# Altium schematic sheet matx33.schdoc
size 594 x 419 mm; Symbol: Drawing-Symbol_A4; @Project Name: Inverted_MAML_6x6; @Page Count: 1; @Update Date: 2026-06-14; @Create Date: 2026-06-14; @Schematic Name: Schematic1; @Page No: 1; @Page Name: P1; Company: EasyEDA.com; Version: V1.0; Page Size: A4; Drawn: Olle Welin; Device: Drawing-Symbol_A4; @Create Time: 14:27:06; @Update Time: 14:27:06; Border: 1; Width: 2338; Height: 1652; Region Start: 1; X Region Count: 6; Y Region Count: 4; Blade Width: 10; Title Block Position: 3
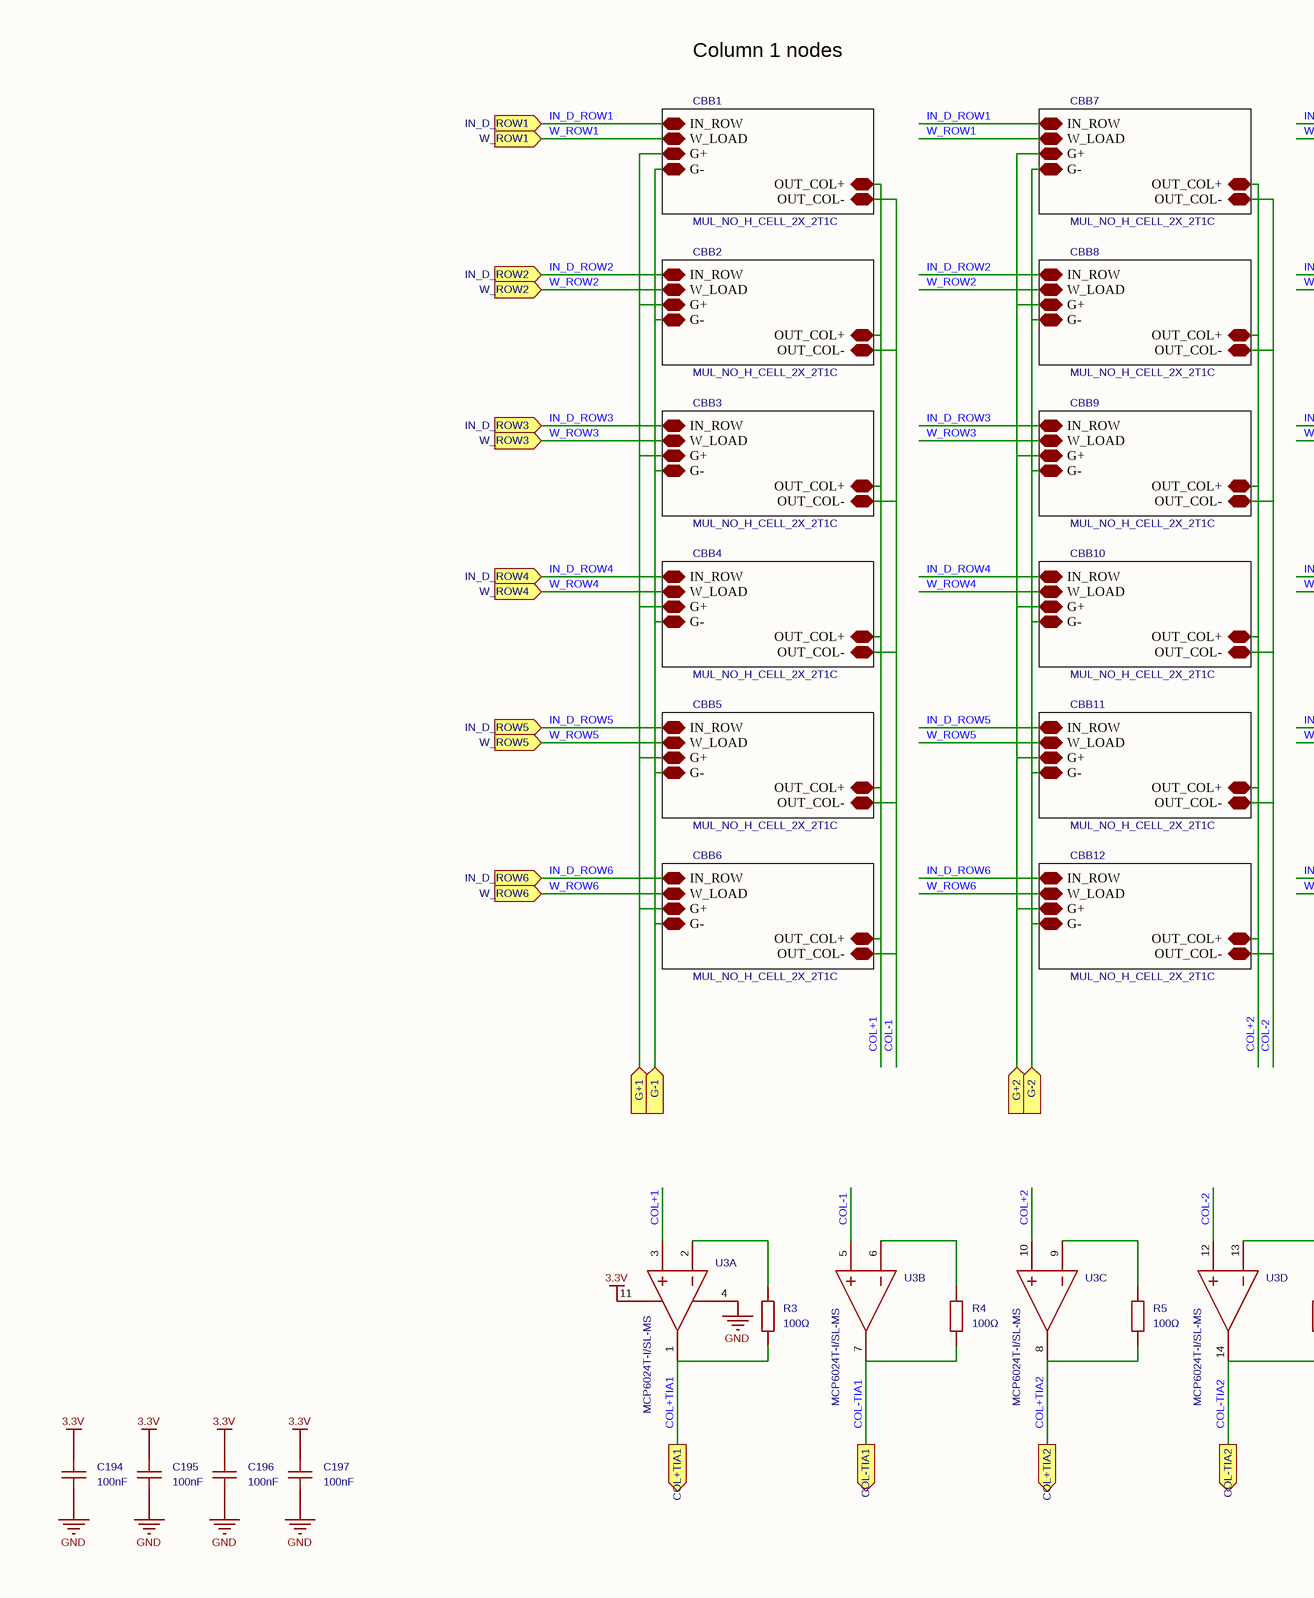
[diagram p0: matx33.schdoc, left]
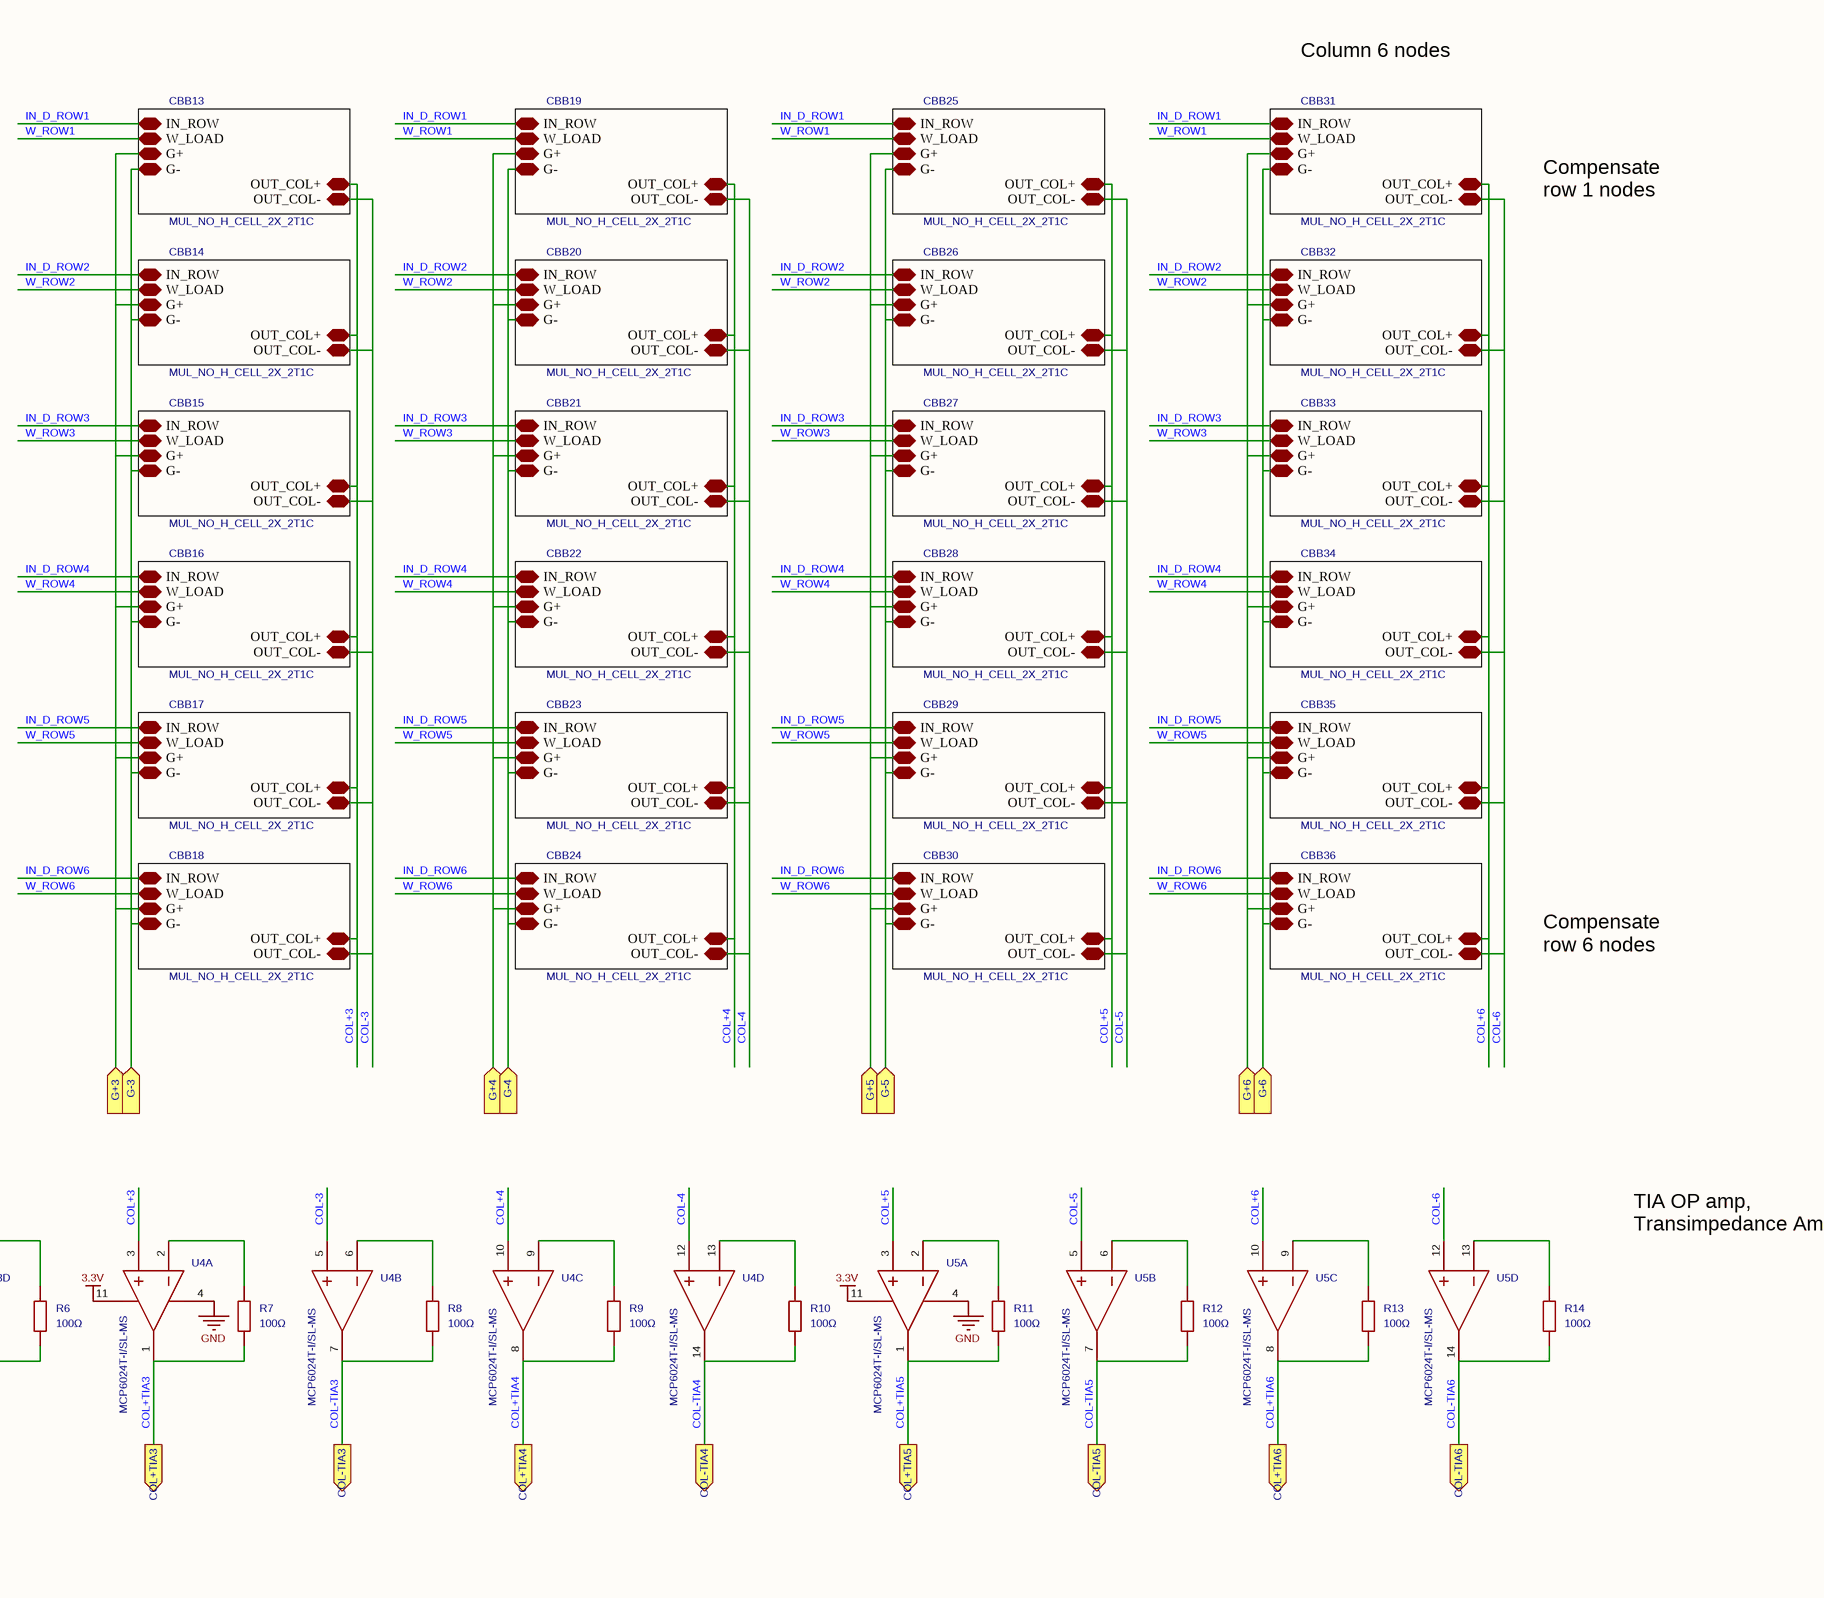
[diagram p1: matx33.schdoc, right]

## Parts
C194  100nF  [C0402]
C195  100nF  [C0402]
C196  100nF  [C0402]
C197  100nF  [C0402]
R3  100Ω  [R0402]
R4  100Ω  [R0402]
R5  100Ω  [R0402]
R6  100Ω  [R0402]
R7  100Ω  [R0402]
R8  100Ω  [R0402]
R9  100Ω  [R0402]
R10  100Ω  [R0402]
R11  100Ω  [R0402]
R12  100Ω  [R0402]
R13  100Ω  [R0402]
R14  100Ω  [R0402]
U3  MCP6024T-I/SL-MS  [SOIC-14_L8.7-W3.9-P1.27-LS6.0-BL-1]  (parts A,B,C,D of 4)
U4  MCP6024T-I/SL-MS  [SOIC-14_L8.7-W3.9-P1.27-LS6.0-BL-1]  (parts A,B,C,D of 4)
U5  MCP6024T-I/SL-MS  [SOIC-14_L8.7-W3.9-P1.27-LS6.0-BL-1]  (parts A,B,C,D of 4)

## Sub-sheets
CBB1 = matrix_33_MUL_CELL.schdoc: G+, W_LOAD, IN_ROW, G-, OUT_COL+, OUT_COL-  | Symbol: MUL_NO_H_CELL_2X_2T1C
CBB2 = matrix_33_MUL_CELL.schdoc: G+, W_LOAD, IN_ROW, G-, OUT_COL+, OUT_COL-  | Symbol: MUL_NO_H_CELL_2X_2T1C
CBB3 = matrix_33_MUL_CELL.schdoc: G+, W_LOAD, IN_ROW, G-, OUT_COL+, OUT_COL-  | Symbol: MUL_NO_H_CELL_2X_2T1C
CBB4 = matrix_33_MUL_CELL.schdoc: G+, W_LOAD, IN_ROW, G-, OUT_COL+, OUT_COL-  | Symbol: MUL_NO_H_CELL_2X_2T1C
CBB5 = matrix_33_MUL_CELL.schdoc: G+, W_LOAD, IN_ROW, G-, OUT_COL+, OUT_COL-  | Symbol: MUL_NO_H_CELL_2X_2T1C
CBB6 = matrix_33_MUL_CELL.schdoc: G+, W_LOAD, IN_ROW, G-, OUT_COL+, OUT_COL-  | Symbol: MUL_NO_H_CELL_2X_2T1C
CBB7 = matrix_33_MUL_CELL.schdoc: G+, W_LOAD, IN_ROW, G-, OUT_COL+, OUT_COL-  | Symbol: MUL_NO_H_CELL_2X_2T1C
CBB8 = matrix_33_MUL_CELL.schdoc: G+, W_LOAD, IN_ROW, G-, OUT_COL+, OUT_COL-  | Symbol: MUL_NO_H_CELL_2X_2T1C
CBB9 = matrix_33_MUL_CELL.schdoc: G+, W_LOAD, IN_ROW, G-, OUT_COL+, OUT_COL-  | Symbol: MUL_NO_H_CELL_2X_2T1C
CBB10 = matrix_33_MUL_CELL.schdoc: G+, W_LOAD, IN_ROW, G-, OUT_COL+, OUT_COL-  | Symbol: MUL_NO_H_CELL_2X_2T1C
CBB11 = matrix_33_MUL_CELL.schdoc: G+, W_LOAD, IN_ROW, G-, OUT_COL+, OUT_COL-  | Symbol: MUL_NO_H_CELL_2X_2T1C
CBB12 = matrix_33_MUL_CELL.schdoc: G+, W_LOAD, IN_ROW, G-, OUT_COL+, OUT_COL-  | Symbol: MUL_NO_H_CELL_2X_2T1C
CBB13 = matrix_33_MUL_CELL.schdoc: G+, W_LOAD, IN_ROW, G-, OUT_COL+, OUT_COL-  | Symbol: MUL_NO_H_CELL_2X_2T1C
CBB14 = matrix_33_MUL_CELL.schdoc: G+, W_LOAD, IN_ROW, G-, OUT_COL+, OUT_COL-  | Symbol: MUL_NO_H_CELL_2X_2T1C
CBB15 = matrix_33_MUL_CELL.schdoc: G+, W_LOAD, IN_ROW, G-, OUT_COL+, OUT_COL-  | Symbol: MUL_NO_H_CELL_2X_2T1C
CBB16 = matrix_33_MUL_CELL.schdoc: G+, W_LOAD, IN_ROW, G-, OUT_COL+, OUT_COL-  | Symbol: MUL_NO_H_CELL_2X_2T1C
CBB17 = matrix_33_MUL_CELL.schdoc: G+, W_LOAD, IN_ROW, G-, OUT_COL+, OUT_COL-  | Symbol: MUL_NO_H_CELL_2X_2T1C
CBB18 = matrix_33_MUL_CELL.schdoc: G+, W_LOAD, IN_ROW, G-, OUT_COL+, OUT_COL-  | Symbol: MUL_NO_H_CELL_2X_2T1C
CBB19 = matrix_33_MUL_CELL.schdoc: G+, W_LOAD, IN_ROW, G-, OUT_COL+, OUT_COL-  | Symbol: MUL_NO_H_CELL_2X_2T1C
CBB20 = matrix_33_MUL_CELL.schdoc: G+, W_LOAD, IN_ROW, G-, OUT_COL+, OUT_COL-  | Symbol: MUL_NO_H_CELL_2X_2T1C
CBB21 = matrix_33_MUL_CELL.schdoc: G+, W_LOAD, IN_ROW, G-, OUT_COL+, OUT_COL-  | Symbol: MUL_NO_H_CELL_2X_2T1C
CBB22 = matrix_33_MUL_CELL.schdoc: G+, W_LOAD, IN_ROW, G-, OUT_COL+, OUT_COL-  | Symbol: MUL_NO_H_CELL_2X_2T1C
CBB23 = matrix_33_MUL_CELL.schdoc: G+, W_LOAD, IN_ROW, G-, OUT_COL+, OUT_COL-  | Symbol: MUL_NO_H_CELL_2X_2T1C
CBB24 = matrix_33_MUL_CELL.schdoc: G+, W_LOAD, IN_ROW, G-, OUT_COL+, OUT_COL-  | Symbol: MUL_NO_H_CELL_2X_2T1C
CBB25 = matrix_33_MUL_CELL.schdoc: G+, W_LOAD, IN_ROW, G-, OUT_COL+, OUT_COL-  | Symbol: MUL_NO_H_CELL_2X_2T1C
CBB26 = matrix_33_MUL_CELL.schdoc: G+, W_LOAD, IN_ROW, G-, OUT_COL+, OUT_COL-  | Symbol: MUL_NO_H_CELL_2X_2T1C
CBB27 = matrix_33_MUL_CELL.schdoc: G+, W_LOAD, IN_ROW, G-, OUT_COL+, OUT_COL-  | Symbol: MUL_NO_H_CELL_2X_2T1C
CBB28 = matrix_33_MUL_CELL.schdoc: G+, W_LOAD, IN_ROW, G-, OUT_COL+, OUT_COL-  | Symbol: MUL_NO_H_CELL_2X_2T1C
CBB29 = matrix_33_MUL_CELL.schdoc: G+, W_LOAD, IN_ROW, G-, OUT_COL+, OUT_COL-  | Symbol: MUL_NO_H_CELL_2X_2T1C
CBB30 = matrix_33_MUL_CELL.schdoc: G+, W_LOAD, IN_ROW, G-, OUT_COL+, OUT_COL-  | Symbol: MUL_NO_H_CELL_2X_2T1C
CBB31 = matrix_33_MUL_CELL.schdoc: G+, W_LOAD, IN_ROW, G-, OUT_COL+, OUT_COL-  | Symbol: MUL_NO_H_CELL_2X_2T1C
CBB32 = matrix_33_MUL_CELL.schdoc: G+, W_LOAD, IN_ROW, G-, OUT_COL+, OUT_COL-  | Symbol: MUL_NO_H_CELL_2X_2T1C
CBB33 = matrix_33_MUL_CELL.schdoc: G+, W_LOAD, IN_ROW, G-, OUT_COL+, OUT_COL-  | Symbol: MUL_NO_H_CELL_2X_2T1C
CBB34 = matrix_33_MUL_CELL.schdoc: G+, W_LOAD, IN_ROW, G-, OUT_COL+, OUT_COL-  | Symbol: MUL_NO_H_CELL_2X_2T1C
CBB35 = matrix_33_MUL_CELL.schdoc: G+, W_LOAD, IN_ROW, G-, OUT_COL+, OUT_COL-  | Symbol: MUL_NO_H_CELL_2X_2T1C
CBB36 = matrix_33_MUL_CELL.schdoc: G+, W_LOAD, IN_ROW, G-, OUT_COL+, OUT_COL-  | Symbol: MUL_NO_H_CELL_2X_2T1C

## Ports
COL+TIA1 (out), COL+TIA2 (out), COL+TIA3 (out), COL+TIA4 (out), COL+TIA5 (out), COL+TIA6 (out), COL-TIA1 (out), COL-TIA2 (out), COL-TIA3 (out), COL-TIA4 (out), COL-TIA5 (out), COL-TIA6 (out), G+1 (in), G+2 (in), G+3 (in), G+4 (in), G+5 (in), G+6 (in), G-1 (in), G-2 (in), G-3 (in), G-4 (in), G-5 (in), G-6 (in), IN_D_ROW1 (in), IN_D_ROW2 (in), IN_D_ROW3 (in), IN_D_ROW4 (in), IN_D_ROW5 (in), IN_D_ROW6 (in), W_ROW1 (in), W_ROW2 (in), W_ROW3 (in), W_ROW4 (in), W_ROW5 (in), W_ROW6 (in)

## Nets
3.3V: C194.2 C195.2 C196.2 C197.2 U3.11(V-) U4.11(V-) U5.11(V-)
GND: C194.1 C195.1 C196.1 C197.1 U3.4(V+) U4.4(V+) U5.4(V+)
COL+1: U3.3(IN1+) ; sheet CBB1/OUT_COL+, sheet CBB3/OUT_COL+, sheet CBB5/OUT_COL+, sheet CBB2/OUT_COL+, sheet CBB4/OUT_COL+, sheet CBB6/OUT_COL+
COL+2: U3.10(IN3+) ; sheet CBB7/OUT_COL+, sheet CBB8/OUT_COL+, sheet CBB9/OUT_COL+, sheet CBB10/OUT_COL+, sheet CBB11/OUT_COL+, sheet CBB12/OUT_COL+
COL+3: U4.3(IN1+) ; sheet CBB13/OUT_COL+, sheet CBB14/OUT_COL+, sheet CBB15/OUT_COL+, sheet CBB16/OUT_COL+, sheet CBB17/OUT_COL+, sheet CBB18/OUT_COL+
COL+4: U4.10(IN3+) ; sheet CBB19/OUT_COL+, sheet CBB20/OUT_COL+, sheet CBB21/OUT_COL+, sheet CBB22/OUT_COL+, sheet CBB23/OUT_COL+, sheet CBB24/OUT_COL+
COL+5: U5.3(IN1+) ; sheet CBB25/OUT_COL+, sheet CBB26/OUT_COL+, sheet CBB27/OUT_COL+, sheet CBB28/OUT_COL+, sheet CBB29/OUT_COL+, sheet CBB30/OUT_COL+
COL+6: U5.10(IN3+) ; sheet CBB31/OUT_COL+, sheet CBB32/OUT_COL+, sheet CBB33/OUT_COL+, sheet CBB34/OUT_COL+, sheet CBB35/OUT_COL+, sheet CBB36/OUT_COL+
COL+TIA1: R3.1 U3.1(OUT1) ; port COL+TIA1
COL+TIA2: R5.1 U3.8(OUT3) ; port COL+TIA2
COL+TIA3: R7.1 U4.1(OUT1) ; port COL+TIA3
COL+TIA4: R9.1 U4.8(OUT3) ; port COL+TIA4
COL+TIA5: R11.1 U5.1(OUT1) ; port COL+TIA5
COL+TIA6: R13.1 U5.8(OUT3) ; port COL+TIA6
COL-1: U3.5(IN2+) ; sheet CBB1/OUT_COL-, sheet CBB3/OUT_COL-, sheet CBB5/OUT_COL-, sheet CBB2/OUT_COL-, sheet CBB4/OUT_COL-, sheet CBB6/OUT_COL-
COL-2: U3.12(IN4+) ; sheet CBB7/OUT_COL-, sheet CBB8/OUT_COL-, sheet CBB9/OUT_COL-, sheet CBB10/OUT_COL-, sheet CBB11/OUT_COL-, sheet CBB12/OUT_COL-
COL-3: U4.5(IN2+) ; sheet CBB13/OUT_COL-, sheet CBB14/OUT_COL-, sheet CBB15/OUT_COL-, sheet CBB16/OUT_COL-, sheet CBB17/OUT_COL-, sheet CBB18/OUT_COL-
COL-4: U4.12(IN4+) ; sheet CBB19/OUT_COL-, sheet CBB20/OUT_COL-, sheet CBB21/OUT_COL-, sheet CBB22/OUT_COL-, sheet CBB23/OUT_COL-, sheet CBB24/OUT_COL-
COL-5: U5.5(IN2+) ; sheet CBB25/OUT_COL-, sheet CBB26/OUT_COL-, sheet CBB27/OUT_COL-, sheet CBB28/OUT_COL-, sheet CBB29/OUT_COL-, sheet CBB30/OUT_COL-
COL-6: U5.12(IN4+) ; sheet CBB31/OUT_COL-, sheet CBB32/OUT_COL-, sheet CBB33/OUT_COL-, sheet CBB34/OUT_COL-, sheet CBB35/OUT_COL-, sheet CBB36/OUT_COL-
COL-TIA1: R4.1 U3.7(OUT2) ; port COL-TIA1
COL-TIA2: R6.1 U3.14(OUT4) ; port COL-TIA2
COL-TIA3: R8.1 U4.7(OUT2) ; port COL-TIA3
COL-TIA4: R10.1 U4.14(OUT4) ; port COL-TIA4
COL-TIA5: R12.1 U5.7(OUT2) ; port COL-TIA5
COL-TIA6: R14.1 U5.14(OUT4) ; port COL-TIA6
G+1: port G+1, sheet CBB1/G+, sheet CBB3/G+, sheet CBB5/G+, sheet CBB2/G+, sheet CBB4/G+, sheet CBB6/G+
G+2: port G+2, sheet CBB7/G+, sheet CBB8/G+, sheet CBB9/G+, sheet CBB10/G+, sheet CBB11/G+, sheet CBB12/G+
G+3: port G+3, sheet CBB13/G+, sheet CBB14/G+, sheet CBB15/G+, sheet CBB16/G+, sheet CBB17/G+, sheet CBB18/G+
G+4: port G+4, sheet CBB19/G+, sheet CBB20/G+, sheet CBB21/G+, sheet CBB22/G+, sheet CBB23/G+, sheet CBB24/G+
G+5: port G+5, sheet CBB25/G+, sheet CBB26/G+, sheet CBB27/G+, sheet CBB28/G+, sheet CBB29/G+, sheet CBB30/G+
G+6: port G+6, sheet CBB31/G+, sheet CBB32/G+, sheet CBB33/G+, sheet CBB34/G+, sheet CBB35/G+, sheet CBB36/G+
G-1: port G-1, sheet CBB1/G-, sheet CBB3/G-, sheet CBB5/G-, sheet CBB2/G-, sheet CBB4/G-, sheet CBB6/G-
G-2: port G-2, sheet CBB7/G-, sheet CBB8/G-, sheet CBB9/G-, sheet CBB10/G-, sheet CBB11/G-, sheet CBB12/G-
G-3: port G-3, sheet CBB13/G-, sheet CBB14/G-, sheet CBB15/G-, sheet CBB16/G-, sheet CBB17/G-, sheet CBB18/G-
G-4: port G-4, sheet CBB19/G-, sheet CBB20/G-, sheet CBB21/G-, sheet CBB22/G-, sheet CBB23/G-, sheet CBB24/G-
G-5: port G-5, sheet CBB25/G-, sheet CBB26/G-, sheet CBB27/G-, sheet CBB28/G-, sheet CBB29/G-, sheet CBB30/G-
G-6: port G-6, sheet CBB31/G-, sheet CBB32/G-, sheet CBB33/G-, sheet CBB34/G-, sheet CBB35/G-, sheet CBB36/G-
IN_D_ROW1: port IN_D_ROW1, sheet CBB1/IN_ROW, sheet CBB7/IN_ROW, sheet CBB13/IN_ROW, sheet CBB19/IN_ROW, sheet CBB25/IN_ROW, sheet CBB31/IN_ROW
IN_D_ROW2: port IN_D_ROW2, sheet CBB8/IN_ROW, sheet CBB14/IN_ROW, sheet CBB20/IN_ROW, sheet CBB26/IN_ROW, sheet CBB32/IN_ROW, sheet CBB2/IN_ROW
IN_D_ROW3: port IN_D_ROW3, sheet CBB3/IN_ROW, sheet CBB9/IN_ROW, sheet CBB15/IN_ROW, sheet CBB21/IN_ROW, sheet CBB27/IN_ROW, sheet CBB33/IN_ROW
IN_D_ROW4: port IN_D_ROW4, sheet CBB10/IN_ROW, sheet CBB16/IN_ROW, sheet CBB22/IN_ROW, sheet CBB28/IN_ROW, sheet CBB34/IN_ROW, sheet CBB4/IN_ROW
IN_D_ROW5: port IN_D_ROW5, sheet CBB5/IN_ROW, sheet CBB11/IN_ROW, sheet CBB17/IN_ROW, sheet CBB23/IN_ROW, sheet CBB29/IN_ROW, sheet CBB35/IN_ROW
IN_D_ROW6: port IN_D_ROW6, sheet CBB12/IN_ROW, sheet CBB18/IN_ROW, sheet CBB24/IN_ROW, sheet CBB30/IN_ROW, sheet CBB36/IN_ROW, sheet CBB6/IN_ROW
W_ROW1: port W_ROW1, sheet CBB1/W_LOAD, sheet CBB7/W_LOAD, sheet CBB13/W_LOAD, sheet CBB19/W_LOAD, sheet CBB25/W_LOAD, sheet CBB31/W_LOAD
W_ROW2: port W_ROW2, sheet CBB8/W_LOAD, sheet CBB14/W_LOAD, sheet CBB20/W_LOAD, sheet CBB26/W_LOAD, sheet CBB32/W_LOAD, sheet CBB2/W_LOAD
W_ROW3: port W_ROW3, sheet CBB3/W_LOAD, sheet CBB9/W_LOAD, sheet CBB15/W_LOAD, sheet CBB21/W_LOAD, sheet CBB27/W_LOAD, sheet CBB33/W_LOAD
W_ROW4: port W_ROW4, sheet CBB10/W_LOAD, sheet CBB16/W_LOAD, sheet CBB22/W_LOAD, sheet CBB28/W_LOAD, sheet CBB34/W_LOAD, sheet CBB4/W_LOAD
W_ROW5: port W_ROW5, sheet CBB5/W_LOAD, sheet CBB11/W_LOAD, sheet CBB17/W_LOAD, sheet CBB23/W_LOAD, sheet CBB29/W_LOAD, sheet CBB35/W_LOAD
W_ROW6: port W_ROW6, sheet CBB12/W_LOAD, sheet CBB18/W_LOAD, sheet CBB24/W_LOAD, sheet CBB30/W_LOAD, sheet CBB36/W_LOAD, sheet CBB6/W_LOAD
NetR3_2: R3.2 U3.2(IN1-)
NetR4_2: R4.2 U3.6(IN2-)
NetR5_2: R5.2 U3.9(IN3-)
NetR6_2: R6.2 U3.13(IN4-)
NetR7_2: R7.2 U4.2(IN1-)
NetR8_2: R8.2 U4.6(IN2-)
NetR9_2: R9.2 U4.9(IN3-)
NetR10_2: R10.2 U4.13(IN4-)
NetR11_2: R11.2 U5.2(IN1-)
NetR12_2: R12.2 U5.6(IN2-)
NetR13_2: R13.2 U5.9(IN3-)
NetR14_2: R14.2 U5.13(IN4-)

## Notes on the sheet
- Column 1 nodes
- Column 6 nodes
- Compensate
  row 1 nodes
- Compensate
  row 6 nodes
- TIA OP amp,
  Transimpedance Amplifier

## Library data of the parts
C194-C197 = CL05B104KO5NNNC: Capacitance:100nF Tolerance:±10% Tolerance:±10% Voltage Rating:16V Temperature Coefficient:X7R; Manufacturer: SAMSUNG(三星); 3D Model: b7d13df3e9464d7a99d0651d1a5b4d570819f05c4eef4c71ace90d822a990e87; 3D Model Transform: 39.37,19.685,0,0,0,0,0,0,0; Tolerance: ±10%; Voltage Rating: 16V; Temperature Coefficient: X7R; AddInBom: yes; ModelName: C0402_L1.0-W0.5-H0.5
R3-R14 = 0402WGF1000TCE: Type:Thick Film Resistors Resistance: Tolerance:±1% Tolerance:±1% Power(Watts): Overload Voltage (Max): Temperature Coefficient:±200ppm/℃ Temperature Coefficient:±200ppm/℃ Operating Temperature Range:-55℃~+155℃ Operating Temperature Range:-55℃~+155℃; Manufacturer: UNI-ROYAL(厚声); 3D Model: efdecb7dae4442949d28eecaf748420f0819f05c4eef4c71ace90d822a990e87; 3D Model Transform: 39.37,19.685,0,0,0,0,0,0,0; Tolerance: ±1%; AddInBom: yes; ModelName: R0402_L1.0-W0.5-H0.4
U3-U5 = MCP6024T-I/SL-MS: Manufacturer: MSKSEMI(美森科); Relevance: []; AddInBom: yes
